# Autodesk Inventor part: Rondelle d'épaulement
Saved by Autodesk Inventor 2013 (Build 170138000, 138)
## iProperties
Created: 2012-12
Part Number: Rondelle d'épaulement
Material: Générique
Document SubType Name: Modeling
Designer: jost thierry
Density: 1 g/cm^3
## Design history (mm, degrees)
node "Rondelle d'épaulement1"
node "Rondelle d'épaulement"
node "Base1"
